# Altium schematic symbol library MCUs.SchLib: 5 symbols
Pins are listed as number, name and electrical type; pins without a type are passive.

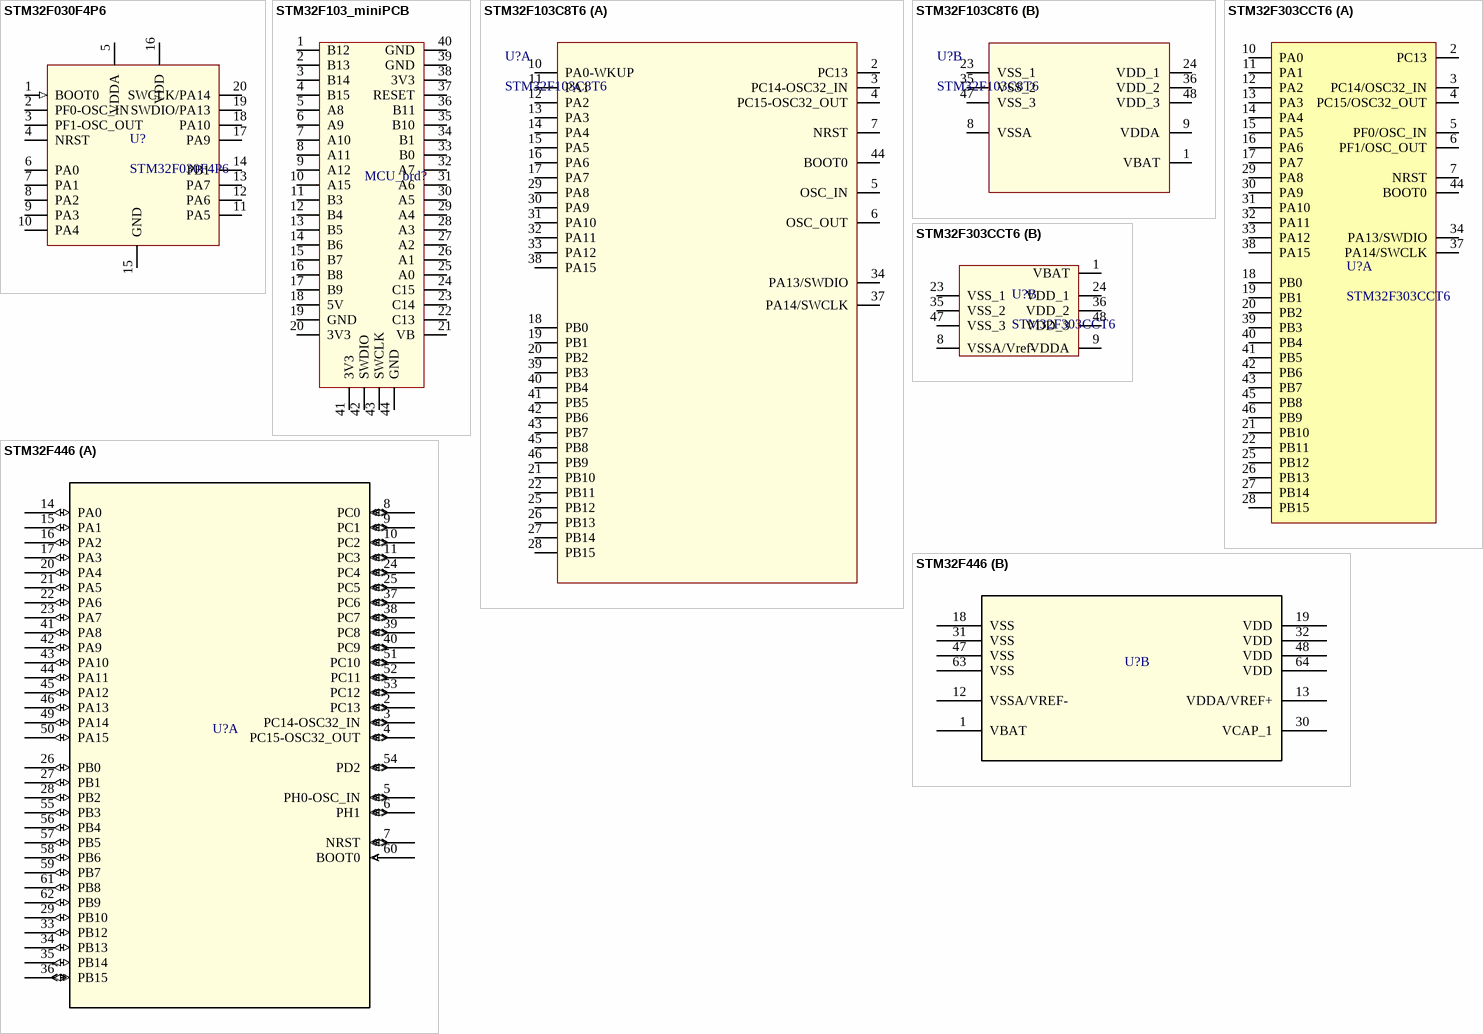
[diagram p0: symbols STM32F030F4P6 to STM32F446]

## STM32F030F4P6
designator U?
footprint TSSOP20 (TSSOP, 20-Leads, Body 6,50x4,40mm, Pitch 0,65mm)
pins: 1 BOOT0 (in), 2 PF0-OSC_IN, 3 PF1-OSC_OUT, 4 NRST, 5 VDDA, 6 PA0, 7 PA1, 8 PA2, 9 PA3, 10 PA4, 11 PA5, 12 PA6, 13 PA7, 14 PB1, 15 GND, 16 VDD, 17 PA9, 18 PA10, 19 SWDIO/PA13, 20 SWCLK/PA14

## STM32F103_miniPCB
designator MCU_brd?  (value not drawn)
STM32 F103C8T6 board
footprint STM32F103C8T6_BOARD
pins: 1 B12, 2 B13, 3 B14, 4 B15, 5 A8, 6 A9, 7 A10, 8 A11, 9 A12, 10 A15, 11 B3, 12 B4, 13 B5, 14 B6, 15 B7, 16 B8, 17 B9, 18 5V, 19 GND, 20 3V3, 21 VB, 22 C13, 23 C14, 24 C15, 25 A0, 26 A1, 27 A2, 28 A3, 29 A4, 30 A5, 31 A6, 32 A7, 33 B0, 34 B1, 35 B10, 36 B11, 37 RESET, 38 3V3, 39 GND, 40 GND, 41 3V3, 42 SWDIO, 43 SWCLK, 44 GND

## STM32F103C8T6
designator U?
No Description Available; Manufacturer_Part_Number: stm32f103cxt2; Vendor: STMicroelectronics
footprint LQFP48_7x7
part A pins: 2 PC13, 3 PC14-OSC32_IN, 4 PC15-OSC32_OUT, 5 OSC_IN, 6 OSC_OUT, 7 NRST, 10 PA0-WKUP, 11 PA1, 12 PA2, 13 PA3, 14 PA4, 15 PA5, 16 PA6, 17 PA7, 18 PB0, 19 PB1, 20 PB2, 21 PB10, 22 PB11, 25 PB12, 26 PB13, 27 PB14, 28 PB15, 29 PA8, 30 PA9, 31 PA10, 32 PA11, 33 PA12, 34 PA13/SWDIO, 37 PA14/SWCLK, 38 PA15, 39 PB3, 40 PB4, 41 PB5, 42 PB6, 43 PB7, 44 BOOT0, 45 PB8, 46 PB9
part B pins: 1 VBAT (power), 8 VSSA (power), 9 VDDA (power), 23 VSS_1 (power), 24 VDD_1 (power), 35 VSS_2 (power), 36 VDD_2 (power), 47 VSS_3 (power), 48 VDD_3 (power)

## STM32F303CCT6
designator U?
footprint LQFP48_7x7
part A pins: 2 PC13, 3 PC14/OSC32_IN, 4 PC15/OSC32_OUT, 5 PF0/OSC_IN, 6 PF1/OSC_OUT, 7 NRST, 10 PA0, 11 PA1, 12 PA2, 13 PA3, 14 PA4, 15 PA5, 16 PA6, 17 PA7, 18 PB0, 19 PB1, 20 PB2, 21 PB10, 22 PB11, 25 PB12, 26 PB13, 27 PB14, 28 PB15, 29 PA8, 30 PA9, 31 PA10, 32 PA11, 33 PA12, 34 PA13/SWDIO, 37 PA14/SWCLK, 38 PA15, 39 PB3, 40 PB4, 41 PB5, 42 PB6, 43 PB7, 44 BOOT0, 45 PB8, 46 PB9
part B pins: 1 VBAT, 8 VSSA/Vref-, 9 VDDA, 23 VSS_1, 24 VDD_1, 35 VSS_2, 36 VDD_2, 47 VSS_3, 48 VDD_3

## STM32F446
designator U?  (value not drawn)
footprint LQFP64_10x10
part A pins: 2 PC13 (io), 3 PC14-OSC32_IN (io), 4 PC15-OSC32_OUT (io), 5 PH0-OSC_IN (io), 6 PH1 (io), 7 NRST (io), 8 PC0 (io), 9 PC1 (io), 10 PC2 (io), 11 PC3 (io), 14 PA0 (io), 15 PA1 (io), 16 PA2 (io), 17 PA3 (io), 20 PA4 (io), 21 PA5 (io), 22 PA6 (io), 23 PA7 (io), 24 PC4 (io), 25 PC5 (io), 26 PB0 (io), 27 PB1 (io), 28 PB2 (io), 29 PB10 (io), 33 PB12 (io), 34 PB13 (io), 35 PB14 (io), 36 PB15 (io), 37 PC6 (io), 38 PC7 (io), 39 PC8 (io), 40 PC9 (io), 41 PA8 (io), 42 PA9 (io), 43 PA10 (io), 44 PA11 (io), 45 PA12 (io), 46 PA13 (io), 49 PA14 (io), 50 PA15 (io), 51 PC10 (io), 52 PC11 (io), 53 PC12 (io), 54 PD2 (io), 55 PB3 (io), 56 PB4 (io), 57 PB5 (io), 58 PB6 (io), 59 PB7 (io), 60 BOOT0 (in), 61 PB8 (io), 62 PB9 (io)
part B pins: 1 VBAT (power), 12 VSSA/VREF- (power), 13 VDDA/VREF+ (power), 18 VSS (power), 19 VDD (power), 30 VCAP_1 (power), 31 VSS (power), 32 VDD (power), 47 VSS (power), 48 VDD (power), 63 VSS (power), 64 VDD (power)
